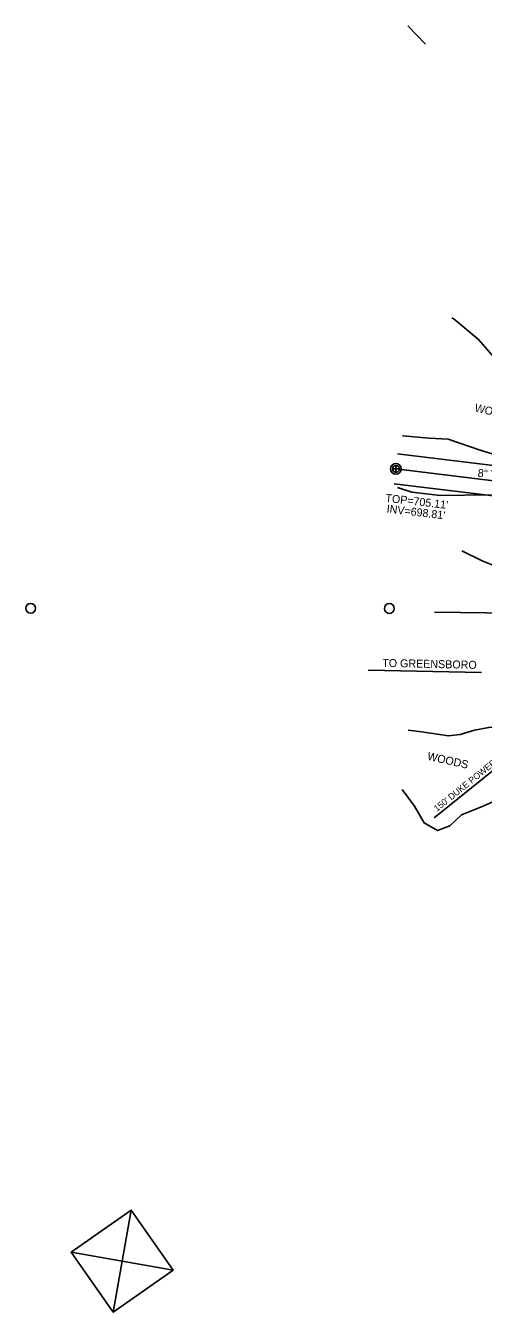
# Model space of a CAD drawing. Extents: x 1784037 to 1786391, y 840555 to 842045.
# Drawn here: x 1784604 to 1784833, y 841243 to 841886 of the extents above; entities that cross this region are included whole.
import ezdxf

# ---------------------------------------------------------------- set-up
doc = ezdxf.new("R2010")
doc.units = 0
for name, color, linetype in [('Exist Right of Way Easement Line', 7, 'Continuous'), ('Exist Right of Way Line', 7, 'Continuous'), ('Exist Right of Way Line Text', 7, 'Continuous'), ('Exist Roads EOP Leader', 7, 'Continuous'), ('Exist Roads EOP Text', 7, 'Continuous'), ('Exist Structure Minor Culvert Topo', 7, 'Continuous'), ('Exist Utilities Other Pole CELL', 7, 'Continuous'), ('Exist Utilities Power Tower CELL', 7, 'Continuous'), ('Exist Utilities Sanitary Sewer Manhole CELL', 7, 'Continuous'), ('Exist Utilities Sanitary Sewer Manhole Top Elevation', 7, 'Continuous'), ('Exist Utilities Sanitary Sewer UG Line', 7, 'Continuous'), ('Exist Utilities Sanitary Sewer UG Line Invert Elevation', 7, 'Continuous'), ('Exist Utilities Sanitary Sewer UG Line Text', 7, 'Continuous'), ('Exist Vegetation Woods Line', 7, 'Continuous'), ('Exist Vegetation Woods Line Text', 7, 'Continuous')]:
    doc.layers.add(name, color=color, linetype=linetype)

msp = doc.modelspace()

# ---------------------------------------------------------------- linework, layer by layer
at = {"layer": 'Exist Right of Way Easement Line'}
for p, q in [((1784790.21, 841671.59), (1785017.35, 841644.05)), ((1784788.41, 841656.7), (1785034.09, 841626.91))]:
    msp.add_line(p, q, dxfattribs=at)
at = {"layer": 'Exist Right of Way Line'}
for p, q in [((1784808.58, 841592.57), (1784955.06, 841590.68)), ((1784862.9, 841533.54), (1784808.49, 841489.81))]:
    msp.add_line(p, q, dxfattribs=at)
at = {"layer": 'Exist Roads EOP Leader'}
msp.add_line((1784775.48, 841563.58), (1784832.13, 841562.44), dxfattribs=at)
at = {"layer": 'Exist Structure Minor Culvert Topo'}
msp.add_line((1784795.36, 841885.62), (1784804.16, 841876.41), dxfattribs=at)
at = {"layer": 'Exist Utilities Other Pole CELL'}
for centre in [(1784606.65, 841594.47), (1784786.03, 841594.37)]:
    msp.add_circle(centre, 2.46, dxfattribs=at)
at = {"layer": 'Exist Utilities Power Tower CELL'}
msp.add_lwpolyline([(1784647.94, 841242.62), (1784677.95, 841263.71), (1784656.86, 841293.71), (1784626.86, 841272.62), (1784647.94, 841242.62), (1784656.86, 841293.71), (1784626.86, 841272.62), (1784677.95, 841263.71)], dxfattribs=at)
at = {"layer": 'Exist Utilities Sanitary Sewer Manhole CELL'}
msp.add_lwpolyline([(1784789.31, 841665.86), (1784789.31, 841662.43), (1784789.31, 841664.14), (1784791.02, 841664.14), (1784787.6, 841664.14)], dxfattribs=at)
for radius in [2.69, 1.71]:
    msp.add_circle((1784789.31, 841664.14), radius, dxfattribs=at)
at = {"layer": 'Exist Utilities Sanitary Sewer UG Line'}
msp.add_line((1784789.31, 841664.14), (1785075.48, 841629.45), dxfattribs=at)
at = {"layer": 'Exist Vegetation Woods Line'}
for points in [[(1784817.22, 841739.58), (1784818.52, 841738.94), (1784830.64, 841728.87), (1784841.64, 841716.11), (1784850.89, 841703.08), (1784863.44, 841689.55), (1784871.46, 841680.71), (1784878.16, 841671.14), (1784878.05, 841667.86), (1784875.16, 841665.9), (1784865.32, 841664.58), (1784848.27, 841668.38), (1784831.46, 841673.52), (1784815.45, 841679.04), (1784805.94, 841679.54), (1784792.76, 841680.64), (1784792.63, 841680.67)], [(1784790.21, 841654.8), (1784797.31, 841652.45), (1784811.62, 841650.89), (1784835.84, 841651.11), (1784857.04, 841647.89), (1784882.3, 841641.65), (1784906.48, 841638.04), (1784935.77, 841630.12), (1784957.56, 841627.11), (1784981.7, 841623.79), (1784993.45, 841622.06), (1784997.97, 841619.39), (1784996.92, 841615.61), (1784990.9, 841614.43), (1784972.19, 841613.44), (1784950.12, 841612.96), (1784927.85, 841613.06), (1784894, 841612.98), (1784876.57, 841610.37), (1784865.15, 841608.86), (1784850.86, 841610.88), (1784832.47, 841618.22), (1784822.25, 841623.11)], [(1784795.38, 841533.55), (1784802.15, 841532.7), (1784815.71, 841530.71), (1784821.47, 841531.31), (1784828.63, 841533.54), (1784835.88, 841534.89), (1784845.66, 841535.22), (1784851.51, 841533.19), (1784854.44, 841529.02), (1784855.68, 841524.25), (1784853.83, 841516.94), (1784850.4, 841508.59), (1784844.11, 841500.52), (1784832.22, 841495.16), (1784822.16, 841491.18), (1784816.37, 841485.7), (1784810.07, 841483.39), (1784803.54, 841487.18), (1784798.65, 841495.52), (1784792.38, 841503.89)]]:
    msp.add_lwpolyline(points, dxfattribs=at)

# ---------------------------------------------------------------- texts
at = {"layer": 'Exist Right of Way Line Text'}
msp.add_text("150' DUKE POWER R/W", height=3.2, rotation=38.78586, dxfattribs=at).set_placement((1784809.9, 841492.69))
at = {"layer": 'Exist Roads EOP Text'}
msp.add_text('TO GREENSBORO', height=4, rotation=358.76624, dxfattribs=at).set_placement((1784782.46, 841565.19))
at = {"layer": 'Exist Utilities Sanitary Sewer Manhole Top Elevation'}
msp.add_text("TOP=705.11'", height=4, rotation=353.38231, dxfattribs=at).set_placement((1784783.91, 841647.72))
at = {"layer": 'Exist Utilities Sanitary Sewer UG Line Invert Elevation'}
msp.add_text("INV=698.81'", height=4, rotation=353.38231, dxfattribs=at).set_placement((1784784.55, 841642.3))
at = {"layer": 'Exist Utilities Sanitary Sewer UG Line Text'}
msp.add_text('8" TRUSS', height=4, rotation=353.08811, dxfattribs=at).set_placement((1784830.07, 841660.24))
at = {"layer": 'Exist Vegetation Woods Line Text'}
for p in [(1784828.45, 841692.84), (1784804.75, 841518.78)]:
    msp.add_text('WOODS', height=4, rotation=347.35991, dxfattribs=at).set_placement(p)

doc.saveas('drawing.dxf')
